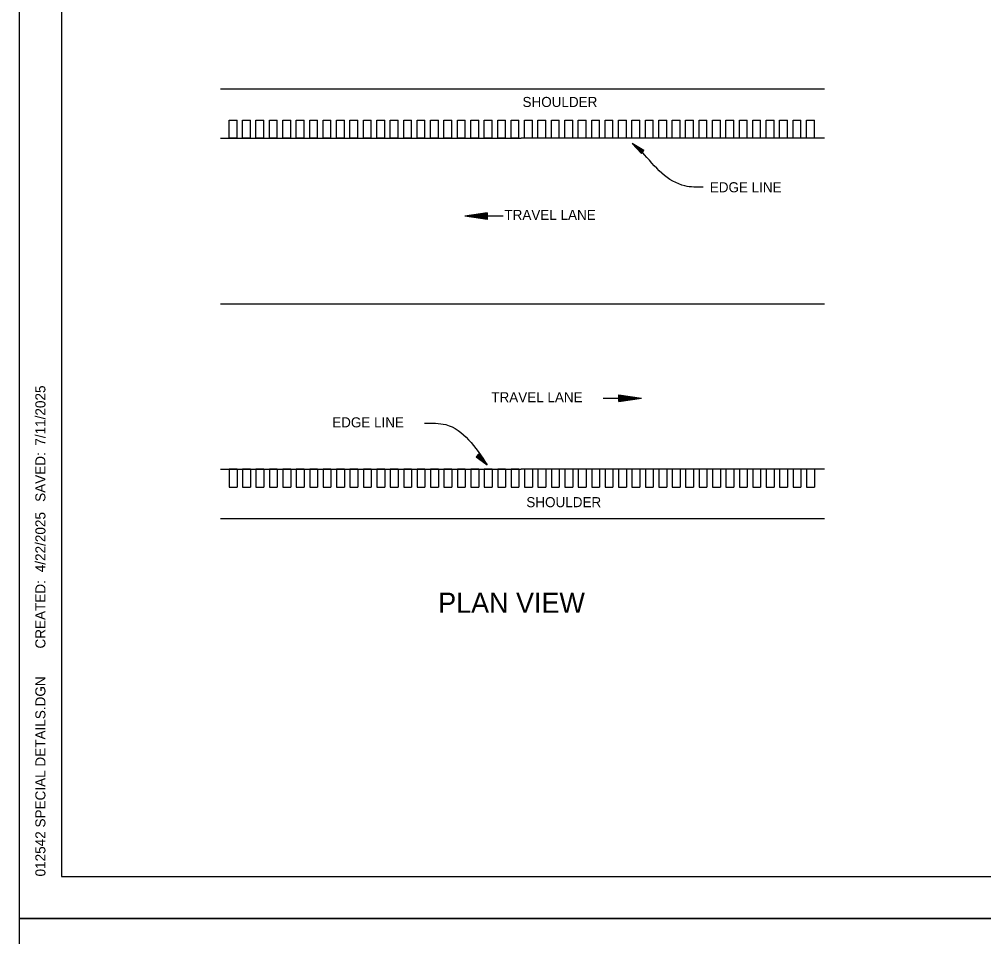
# Model space of a CAD drawing. Extents: x 1371343 to 1373043, y 378740 to 382040.
# Drawn here: x 1371343 to 1371915, y 379830 to 380374 of the extents above; entities that cross this region are included whole.
import ezdxf

# ---------------------------------------------------------------- set-up
doc = ezdxf.new("R2010")
doc.units = 0
for name, color, linetype in [('Default', 7, 'Continuous'), ('E_Existing ROW', 7, 'Continuous'), ('R_Alt Surface Annot', 7, 'Continuous')]:
    doc.layers.add(name, color=color, linetype=linetype)

msp = doc.modelspace()

# ---------------------------------------------------------------- linework, layer by layer
at = {"layer": 'Default'}
for p, q in [((1371462.15, 380332.32), (1371820.21, 380332.32)), ((1371467.32, 380303.13), (1371467.32, 380313.71)), ((1371467.32, 380313.71), (1371471.98, 380313.71)), ((1371471.98, 380303.13), (1371471.98, 380313.71)), ((1371475.28, 380303.13), (1371475.28, 380313.71)), ((1371475.28, 380313.71), (1371479.94, 380313.71)), ((1371479.94, 380303.13), (1371479.94, 380313.71)), ((1371483.24, 380303.13), (1371483.24, 380313.71)), ((1371483.24, 380313.71), (1371487.9, 380313.71)), ((1371487.9, 380303.13), (1371487.9, 380313.71)), ((1371491.2, 380303.13), (1371491.2, 380313.71)), ((1371491.2, 380313.71), (1371495.86, 380313.71)), ((1371495.86, 380303.13), (1371495.86, 380313.71)), ((1371499.16, 380303.13), (1371499.16, 380313.71)), ((1371499.16, 380313.71), (1371503.82, 380313.71)), ((1371503.82, 380303.13), (1371503.82, 380313.71)), ((1371507.12, 380303.13), (1371507.12, 380313.71)), ((1371507.12, 380313.71), (1371511.78, 380313.71)), ((1371511.78, 380303.13), (1371511.78, 380313.71)), ((1371515.08, 380303.13), (1371515.08, 380313.71)), ((1371515.08, 380313.71), (1371519.74, 380313.71)), ((1371519.74, 380303.13), (1371519.74, 380313.71)), ((1371523.04, 380303.13), (1371523.04, 380313.71)), ((1371523.04, 380313.71), (1371527.7, 380313.71)), ((1371527.7, 380303.13), (1371527.7, 380313.71)), ((1371531, 380303.13), (1371531, 380313.71)), ((1371531, 380313.71), (1371535.66, 380313.71)), ((1371535.66, 380303.13), (1371535.66, 380313.71)), ((1371538.96, 380303.13), (1371538.96, 380313.71)), ((1371538.96, 380313.71), (1371543.62, 380313.71)), ((1371543.62, 380303.13), (1371543.62, 380313.71)), ((1371546.92, 380303.13), (1371546.92, 380313.71)), ((1371546.92, 380313.71), (1371551.58, 380313.71)), ((1371551.58, 380303.13), (1371551.58, 380313.71)), ((1371554.88, 380303.13), (1371554.88, 380313.71)), ((1371554.88, 380313.71), (1371559.53, 380313.71)), ((1371559.53, 380303.13), (1371559.53, 380313.71)), ((1371562.84, 380303.13), (1371562.84, 380313.71)), ((1371562.84, 380313.71), (1371567.49, 380313.71)), ((1371567.49, 380303.13), (1371567.49, 380313.71)), ((1371570.8, 380303.13), (1371570.8, 380313.71)), ((1371570.8, 380313.71), (1371575.45, 380313.71)), ((1371575.45, 380303.13), (1371575.45, 380313.71)), ((1371578.76, 380303.13), (1371578.76, 380313.71)), ((1371578.76, 380313.71), (1371583.41, 380313.71)), ((1371583.41, 380303.13), (1371583.41, 380313.71)), ((1371586.72, 380303.13), (1371586.72, 380313.71)), ((1371586.72, 380303.13), (1371586.72, 380313.71)), ((1371586.72, 380313.71), (1371591.37, 380313.71)), ((1371591.37, 380303.13), (1371591.37, 380313.71)), ((1371594.68, 380303.13), (1371594.68, 380313.71)), ((1371594.68, 380313.71), (1371599.33, 380313.71)), ((1371599.33, 380303.13), (1371599.33, 380313.71)), ((1371602.64, 380303.13), (1371602.64, 380313.71)), ((1371602.64, 380313.71), (1371607.29, 380313.71)), ((1371607.29, 380303.13), (1371607.29, 380313.71)), ((1371610.6, 380303.13), (1371610.6, 380313.71)), ((1371610.6, 380313.71), (1371615.25, 380313.71)), ((1371615.25, 380303.13), (1371615.25, 380313.71)), ((1371618.55, 380303.13), (1371618.55, 380313.71)), ((1371618.55, 380313.71), (1371623.21, 380313.71)), ((1371623.21, 380303.13), (1371623.21, 380313.71)), ((1371626.51, 380303.13), (1371626.51, 380313.71)), ((1371626.51, 380313.71), (1371631.17, 380313.71)), ((1371631.17, 380303.13), (1371631.17, 380313.71)), ((1371634.47, 380303.13), (1371634.47, 380313.71)), ((1371634.47, 380313.71), (1371639.13, 380313.71)), ((1371639.13, 380303.13), (1371639.13, 380313.71)), ((1371642.43, 380303.13), (1371642.43, 380313.71)), ((1371642.43, 380313.71), (1371647.09, 380313.71)), ((1371647.09, 380303.13), (1371647.09, 380313.71)), ((1371650.39, 380303.13), (1371650.39, 380313.71)), ((1371650.39, 380313.71), (1371655.05, 380313.71)), ((1371655.05, 380303.13), (1371655.05, 380313.71)), ((1371658.35, 380303.13), (1371658.35, 380313.71)), ((1371658.35, 380313.71), (1371663.01, 380313.71)), ((1371663.01, 380303.13), (1371663.01, 380313.71)), ((1371666.31, 380303.13), (1371666.31, 380313.71)), ((1371666.31, 380313.71), (1371670.97, 380313.71)), ((1371670.97, 380303.13), (1371670.97, 380313.71)), ((1371674.27, 380303.13), (1371674.27, 380313.71)), ((1371674.27, 380313.71), (1371678.93, 380313.71)), ((1371678.93, 380303.13), (1371678.93, 380313.71)), ((1371682.23, 380303.13), (1371682.23, 380313.71)), ((1371682.23, 380313.71), (1371686.89, 380313.71)), ((1371686.89, 380303.13), (1371686.89, 380313.71)), ((1371690.19, 380303.13), (1371690.19, 380313.71)), ((1371690.19, 380313.71), (1371694.85, 380313.71)), ((1371694.85, 380303.13), (1371694.85, 380313.71)), ((1371698.15, 380303.13), (1371698.15, 380313.71)), ((1371698.15, 380313.71), (1371702.81, 380313.71)), ((1371702.81, 380303.13), (1371702.81, 380313.71)), ((1371706.11, 380303.13), (1371706.11, 380313.71)), ((1371706.11, 380313.71), (1371710.77, 380313.71)), ((1371710.77, 380303.13), (1371710.77, 380313.71)), ((1371714.07, 380303.13), (1371714.07, 380313.71)), ((1371714.07, 380313.71), (1371718.73, 380313.71)), ((1371718.73, 380303.13), (1371718.73, 380313.71)), ((1371722.03, 380303.13), (1371722.03, 380313.71)), ((1371722.03, 380313.71), (1371726.69, 380313.71)), ((1371726.69, 380303.13), (1371726.69, 380313.71)), ((1371729.99, 380303.13), (1371729.99, 380313.71)), ((1371729.99, 380313.71), (1371734.64, 380313.71)), ((1371734.64, 380303.13), (1371734.64, 380313.71)), ((1371737.95, 380303.13), (1371737.95, 380313.71)), ((1371737.95, 380313.71), (1371742.6, 380313.71)), ((1371742.6, 380303.13), (1371742.6, 380313.71)), ((1371745.91, 380303.13), (1371745.91, 380313.71)), ((1371745.91, 380313.71), (1371750.56, 380313.71)), ((1371750.56, 380303.13), (1371750.56, 380313.71)), ((1371753.87, 380303.13), (1371753.87, 380313.71)), ((1371753.87, 380313.71), (1371758.52, 380313.71)), ((1371758.52, 380303.13), (1371758.52, 380313.71)), ((1371761.83, 380303.13), (1371761.83, 380313.71)), ((1371761.83, 380313.71), (1371766.48, 380313.71)), ((1371766.48, 380303.13), (1371766.48, 380313.71)), ((1371769.79, 380303.13), (1371769.79, 380313.71)), ((1371769.79, 380313.71), (1371774.44, 380313.71)), ((1371774.44, 380303.13), (1371774.44, 380313.71)), ((1371777.75, 380303.13), (1371777.75, 380313.71)), ((1371777.75, 380313.71), (1371782.4, 380313.71)), ((1371782.4, 380303.13), (1371782.4, 380313.71)), ((1371785.7, 380303.13), (1371785.7, 380313.71)), ((1371785.7, 380313.71), (1371790.36, 380313.71)), ((1371790.36, 380303.13), (1371790.36, 380313.71)), ((1371793.66, 380303.13), (1371793.66, 380313.71)), ((1371793.66, 380313.71), (1371798.32, 380313.71)), ((1371798.32, 380303.13), (1371798.32, 380313.71)), ((1371801.62, 380303.13), (1371801.62, 380313.71)), ((1371801.62, 380313.71), (1371806.28, 380313.71)), ((1371806.28, 380303.13), (1371806.28, 380313.71)), ((1371809.58, 380303.13), (1371809.58, 380313.71)), ((1371809.58, 380313.71), (1371814.24, 380313.71)), ((1371814.24, 380303.13), (1371814.24, 380313.71)), ((1371462.15, 380303.13), (1371640.34, 380303.13)), ((1371471.98, 380303.13), (1371467.32, 380303.13)), ((1371479.94, 380303.13), (1371475.28, 380303.13)), ((1371487.9, 380303.13), (1371483.24, 380303.13)), ((1371495.86, 380303.13), (1371491.2, 380303.13)), ((1371503.82, 380303.13), (1371499.16, 380303.13)), ((1371511.78, 380303.13), (1371507.12, 380303.13)), ((1371519.74, 380303.13), (1371515.08, 380303.13)), ((1371527.7, 380303.13), (1371523.04, 380303.13)), ((1371535.66, 380303.13), (1371531, 380303.13)), ((1371543.62, 380303.13), (1371538.96, 380303.13)), ((1371551.58, 380303.13), (1371546.92, 380303.13)), ((1371559.53, 380303.13), (1371554.88, 380303.13)), ((1371567.49, 380303.13), (1371562.84, 380303.13)), ((1371575.45, 380303.13), (1371570.8, 380303.13)), ((1371583.41, 380303.13), (1371578.76, 380303.13)), ((1371591.37, 380303.13), (1371586.72, 380303.13)), ((1371599.33, 380303.13), (1371594.68, 380303.13)), ((1371607.29, 380303.13), (1371602.64, 380303.13)), ((1371615.25, 380303.13), (1371610.6, 380303.13)), ((1371623.21, 380303.13), (1371618.55, 380303.13)), ((1371631.17, 380303.13), (1371626.51, 380303.13)), ((1371639.13, 380303.13), (1371634.47, 380303.13)), ((1371820.21, 380303.13), (1371640.34, 380303.13)), ((1371647.09, 380303.13), (1371642.43, 380303.13)), ((1371655.05, 380303.13), (1371650.39, 380303.13)), ((1371663.01, 380303.13), (1371658.35, 380303.13)), ((1371670.97, 380303.13), (1371666.31, 380303.13)), ((1371678.93, 380303.13), (1371674.27, 380303.13)), ((1371686.89, 380303.13), (1371682.23, 380303.13)), ((1371694.85, 380303.13), (1371690.19, 380303.13)), ((1371702.81, 380303.13), (1371698.15, 380303.13)), ((1371710.77, 380303.13), (1371706.11, 380303.13)), ((1371718.73, 380303.13), (1371714.07, 380303.13)), ((1371726.69, 380303.13), (1371722.03, 380303.13)), ((1371734.64, 380303.13), (1371729.99, 380303.13)), ((1371742.6, 380303.13), (1371737.95, 380303.13)), ((1371750.56, 380303.13), (1371745.91, 380303.13)), ((1371758.52, 380303.13), (1371753.87, 380303.13)), ((1371766.48, 380303.13), (1371761.83, 380303.13)), ((1371774.44, 380303.13), (1371769.79, 380303.13)), ((1371782.4, 380303.13), (1371777.75, 380303.13)), ((1371790.36, 380303.13), (1371785.7, 380303.13)), ((1371798.32, 380303.13), (1371793.66, 380303.13)), ((1371806.28, 380303.13), (1371801.62, 380303.13)), ((1371814.24, 380303.13), (1371809.58, 380303.13)), ((1371711.7, 380293.95), (1371706.23, 380299.86)), ((1371713.19, 380295.82), (1371706.23, 380299.86)), ((1371711.82, 380294.11), (1371707.26, 380299.03)), ((1371713.07, 380295.66), (1371707.26, 380299.03)), ((1371712.93, 380295.5), (1371708.34, 380298.19)), ((1371711.96, 380294.27), (1371708.34, 380298.19)), ((1371712.08, 380294.43), (1371709.37, 380297.36)), ((1371712.82, 380295.35), (1371709.37, 380297.36)), ((1371712.68, 380295.19), (1371710.43, 380296.5)), ((1371712.2, 380294.59), (1371710.43, 380296.5)), ((1371711.7, 380293.95), (1371713.19, 380295.82)), ((1371712.56, 380295.03), (1371711.46, 380295.68)), ((1371712.32, 380294.75), (1371711.46, 380295.68)), ((1371620.37, 380258.83), (1371606.99, 380256.82)), ((1371629.76, 380256.82), (1371606.99, 380256.82)), ((1371620.37, 380254.83), (1371606.99, 380256.82)), ((1371620.37, 380258.49), (1371609.22, 380256.82)), ((1371620.37, 380255.15), (1371609.22, 380256.82)), ((1371620.37, 380258.17), (1371611.51, 380256.82)), ((1371620.37, 380255.51), (1371611.51, 380256.82)), ((1371620.37, 380257.81), (1371613.72, 380256.82)), ((1371620.37, 380255.82), (1371613.72, 380256.82)), ((1371620.37, 380257.46), (1371616.01, 380256.82)), ((1371620.37, 380256.16), (1371616.01, 380256.82)), ((1371620.37, 380257.16), (1371618.24, 380256.82)), ((1371620.37, 380256.5), (1371618.24, 380256.82)), ((1371620.37, 380258.83), (1371620.37, 380254.83)), ((1371462.15, 380204.96), (1371820.21, 380204.96)), ((1371689.04, 380149.07), (1371711.8, 380149.07)), ((1371698.43, 380151.04), (1371711.8, 380149.07)), ((1371698.43, 380147.06), (1371698.43, 380151.04)), ((1371698.43, 380150.72), (1371709.57, 380149.07)), ((1371698.43, 380150.38), (1371707.28, 380149.07)), ((1371698.43, 380150.04), (1371705.07, 380149.07)), ((1371698.43, 380149.71), (1371702.79, 380149.07)), ((1371698.43, 380149.39), (1371700.56, 380149.07)), ((1371698.43, 380147.06), (1371711.8, 380149.07)), ((1371698.43, 380148.41), (1371702.79, 380149.07)), ((1371698.43, 380147.72), (1371707.28, 380149.07)), ((1371698.43, 380147.38), (1371709.57, 380149.07)), ((1371698.43, 380148.05), (1371705.07, 380149.07)), ((1371698.43, 380148.73), (1371700.56, 380149.07)), ((1371615.37, 380115.92), (1371613.72, 380114.21)), ((1371613.72, 380114.21), (1371620.27, 380109.51)), ((1371613.86, 380114.35), (1371619.31, 380110.45)), ((1371614, 380114.49), (1371618.32, 380111.4)), ((1371614.14, 380114.62), (1371617.38, 380112.32)), ((1371614.28, 380114.76), (1371616.41, 380113.25)), ((1371614.42, 380114.92), (1371615.45, 380114.19)), ((1371614.67, 380115.18), (1371615.45, 380114.19)), ((1371614.81, 380115.32), (1371616.41, 380113.25)), ((1371614.95, 380115.48), (1371617.38, 380112.32)), ((1371615.09, 380115.62), (1371618.32, 380111.4)), ((1371615.23, 380115.76), (1371619.31, 380110.45)), ((1371615.37, 380115.92), (1371620.27, 380109.51)), ((1371462.15, 380106.8), (1371640.34, 380106.8)), ((1371471.98, 380106.8), (1371467.32, 380106.8)), ((1371467.32, 380106.8), (1371467.32, 380096.22)), ((1371471.98, 380106.8), (1371471.98, 380096.22)), ((1371479.94, 380106.8), (1371475.28, 380106.8)), ((1371475.28, 380106.8), (1371475.28, 380096.22)), ((1371479.94, 380106.8), (1371479.94, 380096.22)), ((1371487.9, 380106.8), (1371483.24, 380106.8)), ((1371483.24, 380106.8), (1371483.24, 380096.22)), ((1371487.9, 380106.8), (1371487.9, 380096.22)), ((1371495.86, 380106.8), (1371491.2, 380106.8)), ((1371491.2, 380106.8), (1371491.2, 380096.22)), ((1371495.86, 380106.8), (1371495.86, 380096.22)), ((1371503.82, 380106.8), (1371499.16, 380106.8)), ((1371499.16, 380106.8), (1371499.16, 380096.22)), ((1371503.82, 380106.8), (1371503.82, 380096.22)), ((1371511.78, 380106.8), (1371507.12, 380106.8)), ((1371507.12, 380106.8), (1371507.12, 380096.22)), ((1371511.78, 380106.8), (1371511.78, 380096.22)), ((1371519.74, 380106.8), (1371515.08, 380106.8)), ((1371515.08, 380106.8), (1371515.08, 380096.22)), ((1371519.74, 380106.8), (1371519.74, 380096.22)), ((1371527.7, 380106.8), (1371523.04, 380106.8)), ((1371523.04, 380106.8), (1371523.04, 380096.22)), ((1371527.7, 380106.8), (1371527.7, 380096.22)), ((1371535.66, 380106.8), (1371531, 380106.8)), ((1371531, 380106.8), (1371531, 380096.22)), ((1371535.66, 380106.8), (1371535.66, 380096.22)), ((1371543.62, 380106.8), (1371538.96, 380106.8)), ((1371538.96, 380106.8), (1371538.96, 380096.22)), ((1371543.62, 380106.8), (1371543.62, 380096.22)), ((1371551.58, 380106.8), (1371546.92, 380106.8)), ((1371546.92, 380106.8), (1371546.92, 380096.22)), ((1371551.58, 380106.8), (1371551.58, 380096.22)), ((1371559.53, 380106.8), (1371554.88, 380106.8)), ((1371554.88, 380106.8), (1371554.88, 380096.22)), ((1371559.53, 380106.8), (1371559.53, 380096.22)), ((1371567.49, 380106.8), (1371562.84, 380106.8)), ((1371562.84, 380106.8), (1371562.84, 380096.22)), ((1371567.49, 380106.8), (1371567.49, 380096.22)), ((1371575.45, 380106.8), (1371570.8, 380106.8)), ((1371570.8, 380106.8), (1371570.8, 380096.22)), ((1371575.45, 380106.8), (1371575.45, 380096.22)), ((1371583.41, 380106.8), (1371578.76, 380106.8)), ((1371578.76, 380106.8), (1371578.76, 380096.22)), ((1371583.41, 380106.8), (1371583.41, 380096.22)), ((1371591.37, 380106.8), (1371586.72, 380106.8)), ((1371586.72, 380106.8), (1371586.72, 380096.22)), ((1371591.37, 380106.8), (1371591.37, 380096.22)), ((1371599.33, 380106.8), (1371594.68, 380106.8)), ((1371594.68, 380106.8), (1371594.68, 380096.22)), ((1371599.33, 380106.8), (1371599.33, 380096.22)), ((1371607.29, 380106.8), (1371602.64, 380106.8)), ((1371602.64, 380106.8), (1371602.64, 380096.22)), ((1371607.29, 380106.8), (1371607.29, 380096.22)), ((1371615.25, 380106.8), (1371610.6, 380106.8)), ((1371610.6, 380106.8), (1371610.6, 380096.22)), ((1371615.25, 380106.8), (1371615.25, 380096.22)), ((1371623.21, 380106.8), (1371618.55, 380106.8)), ((1371618.55, 380106.8), (1371618.55, 380096.22)), ((1371623.21, 380106.8), (1371623.21, 380096.22)), ((1371631.17, 380106.8), (1371626.51, 380106.8)), ((1371626.51, 380106.8), (1371626.51, 380096.22)), ((1371631.17, 380106.8), (1371631.17, 380096.22)), ((1371639.13, 380106.8), (1371634.47, 380106.8)), ((1371634.47, 380106.8), (1371634.47, 380096.22)), ((1371639.13, 380106.8), (1371639.13, 380096.22)), ((1371820.21, 380106.8), (1371640.34, 380106.8)), ((1371647.09, 380106.8), (1371642.43, 380106.8)), ((1371642.43, 380106.8), (1371642.43, 380096.22)), ((1371647.09, 380106.8), (1371647.09, 380096.22)), ((1371655.05, 380106.8), (1371650.39, 380106.8)), ((1371650.39, 380106.8), (1371650.39, 380096.22)), ((1371655.05, 380106.8), (1371655.05, 380096.22)), ((1371663.01, 380106.8), (1371658.35, 380106.8)), ((1371658.35, 380106.8), (1371658.35, 380096.22)), ((1371663.01, 380106.8), (1371663.01, 380096.22)), ((1371670.97, 380106.8), (1371666.31, 380106.8)), ((1371666.31, 380106.8), (1371666.31, 380096.22)), ((1371670.97, 380106.8), (1371670.97, 380096.22)), ((1371678.93, 380106.8), (1371674.27, 380106.8)), ((1371674.27, 380106.8), (1371674.27, 380096.22)), ((1371678.93, 380106.8), (1371678.93, 380096.22)), ((1371686.89, 380106.8), (1371682.23, 380106.8)), ((1371682.23, 380106.8), (1371682.23, 380096.22)), ((1371686.89, 380106.8), (1371686.89, 380096.22)), ((1371694.85, 380106.8), (1371690.19, 380106.8)), ((1371690.19, 380106.8), (1371690.19, 380096.22)), ((1371694.85, 380106.8), (1371694.85, 380096.22)), ((1371702.81, 380106.8), (1371698.15, 380106.8)), ((1371698.15, 380106.8), (1371698.15, 380096.22)), ((1371702.81, 380106.8), (1371702.81, 380096.22)), ((1371710.77, 380106.8), (1371706.11, 380106.8)), ((1371706.11, 380106.8), (1371706.11, 380096.22)), ((1371710.77, 380106.8), (1371710.77, 380096.22)), ((1371718.73, 380106.8), (1371714.07, 380106.8)), ((1371714.07, 380106.8), (1371714.07, 380096.22)), ((1371718.73, 380106.8), (1371718.73, 380096.22)), ((1371726.69, 380106.8), (1371722.03, 380106.8)), ((1371722.03, 380106.8), (1371722.03, 380096.22)), ((1371726.69, 380106.8), (1371726.69, 380096.22)), ((1371734.64, 380106.8), (1371729.99, 380106.8)), ((1371729.99, 380106.8), (1371729.99, 380096.22)), ((1371734.64, 380106.8), (1371734.64, 380096.22)), ((1371742.6, 380106.8), (1371737.95, 380106.8)), ((1371737.95, 380106.8), (1371737.95, 380096.22)), ((1371742.6, 380106.8), (1371742.6, 380096.22)), ((1371750.56, 380106.8), (1371745.91, 380106.8)), ((1371745.91, 380106.8), (1371745.91, 380096.22)), ((1371750.56, 380106.8), (1371750.56, 380096.22)), ((1371758.52, 380106.8), (1371753.87, 380106.8)), ((1371753.87, 380106.8), (1371753.87, 380096.22)), ((1371758.52, 380106.8), (1371758.52, 380096.22)), ((1371766.48, 380106.8), (1371761.83, 380106.8)), ((1371761.83, 380106.8), (1371761.83, 380096.22)), ((1371766.48, 380106.8), (1371766.48, 380096.22)), ((1371774.44, 380106.8), (1371769.79, 380106.8)), ((1371769.79, 380106.8), (1371769.79, 380096.22)), ((1371774.44, 380106.8), (1371774.44, 380096.22)), ((1371782.4, 380106.8), (1371777.75, 380106.8)), ((1371777.75, 380106.8), (1371777.75, 380096.22)), ((1371782.4, 380106.8), (1371782.4, 380096.22)), ((1371790.36, 380106.8), (1371785.7, 380106.8)), ((1371785.7, 380106.8), (1371785.7, 380096.22)), ((1371790.36, 380106.8), (1371790.36, 380096.22)), ((1371798.32, 380106.8), (1371793.66, 380106.8)), ((1371793.66, 380106.8), (1371793.66, 380096.22)), ((1371798.32, 380106.8), (1371798.32, 380096.22)), ((1371806.28, 380106.8), (1371801.62, 380106.8)), ((1371801.62, 380106.8), (1371801.62, 380096.22)), ((1371806.28, 380106.8), (1371806.28, 380096.22)), ((1371814.24, 380106.8), (1371809.58, 380106.8)), ((1371809.58, 380106.8), (1371809.58, 380096.22)), ((1371814.24, 380106.8), (1371814.24, 380096.22)), ((1371467.32, 380096.22), (1371471.98, 380096.22)), ((1371475.28, 380096.22), (1371479.94, 380096.22)), ((1371483.24, 380096.22), (1371487.9, 380096.22)), ((1371491.2, 380096.22), (1371495.86, 380096.22)), ((1371499.16, 380096.22), (1371503.82, 380096.22)), ((1371507.12, 380096.22), (1371511.78, 380096.22)), ((1371515.08, 380096.22), (1371519.74, 380096.22)), ((1371523.04, 380096.22), (1371527.7, 380096.22)), ((1371531, 380096.22), (1371535.66, 380096.22)), ((1371538.96, 380096.22), (1371543.62, 380096.22)), ((1371546.92, 380096.22), (1371551.58, 380096.22)), ((1371554.88, 380096.22), (1371559.53, 380096.22)), ((1371562.84, 380096.22), (1371567.49, 380096.22)), ((1371570.8, 380096.22), (1371575.45, 380096.22)), ((1371578.76, 380096.22), (1371583.41, 380096.22)), ((1371586.72, 380096.22), (1371591.37, 380096.22)), ((1371594.68, 380096.22), (1371599.33, 380096.22)), ((1371602.64, 380096.22), (1371607.29, 380096.22)), ((1371610.6, 380096.22), (1371615.25, 380096.22)), ((1371618.55, 380096.22), (1371623.21, 380096.22)), ((1371626.51, 380096.22), (1371631.17, 380096.22)), ((1371634.47, 380096.22), (1371639.13, 380096.22)), ((1371642.43, 380096.22), (1371647.09, 380096.22)), ((1371650.39, 380096.22), (1371655.05, 380096.22)), ((1371658.35, 380096.22), (1371663.01, 380096.22)), ((1371666.31, 380096.22), (1371670.97, 380096.22)), ((1371674.27, 380096.22), (1371678.93, 380096.22)), ((1371682.23, 380096.22), (1371686.89, 380096.22)), ((1371690.19, 380096.22), (1371694.85, 380096.22)), ((1371698.15, 380096.22), (1371702.81, 380096.22)), ((1371706.11, 380096.22), (1371710.77, 380096.22)), ((1371714.07, 380096.22), (1371718.73, 380096.22)), ((1371722.03, 380096.22), (1371726.69, 380096.22)), ((1371729.99, 380096.22), (1371734.64, 380096.22)), ((1371737.95, 380096.22), (1371742.6, 380096.22)), ((1371745.91, 380096.22), (1371750.56, 380096.22)), ((1371753.87, 380096.22), (1371758.52, 380096.22)), ((1371761.83, 380096.22), (1371766.48, 380096.22)), ((1371769.79, 380096.22), (1371774.44, 380096.22)), ((1371777.75, 380096.22), (1371782.4, 380096.22)), ((1371785.7, 380096.22), (1371790.36, 380096.22)), ((1371793.66, 380096.22), (1371798.32, 380096.22)), ((1371801.62, 380096.22), (1371806.28, 380096.22)), ((1371809.58, 380096.22), (1371814.24, 380096.22)), ((1371462.15, 380077.61), (1371820.21, 380077.61))]:
    msp.add_line(p, q, dxfattribs=at)
for points in [[(1371748.3, 380273.99), (1371737.51, 380274.77), (1371712.16, 380294.97)], [(1371583.06, 380134.15), (1371595.73, 380133.27), (1371620.27, 380109.51)]]:
    msp.add_spline(points, degree=3, dxfattribs=at)
at = {"layer": 'E_Existing ROW'}
for points in [[(1371342.92, 379840.49), (1373042.92, 379840.49), (1373042.92, 380940.49), (1371342.92, 380940.49)], [(1371367.92, 379865.49), (1373017.92, 379865.49), (1373017.92, 380915.49), (1371367.92, 380915.49)], [(1371342.92, 378740.49), (1373042.92, 378740.49), (1373042.92, 379840.49), (1371342.92, 379840.49)]]:
    msp.add_lwpolyline(points, close=True, dxfattribs=at)

# ---------------------------------------------------------------- texts
at = {"layer": 'Default'}
for s, height, p in [('SHOULDER', 5.97, (1371641.24, 380321.55)), ('EDGE LINE', 5.97, (1371752.26, 380270.99)), ('TRAVEL LANE', 5.9696, (1371630.51, 380254.62)), ('TRAVEL LANE', 5.9696, (1371622.72, 380146.55)), ('EDGE LINE', 5.97, (1371528.39, 380131.67)), ('SHOULDER', 5.97, (1371643.51, 380084.36)), ('PLAN VIEW ', 11.939, (1371591.25, 380021.75))]:
    msp.add_text(s, height=height, dxfattribs=at).set_placement(p)
at = {"layer": 'R_Alt Surface Annot'}
for s, p in [('7/11/2025', (1371358.42, 380120.8)), ('  SAVED: ', (1371358.42, 380083.06)), ('4/22/2025', (1371358.42, 380045.79)), ('     CREATED: ', (1371358.42, 379989.43)), ('012542 SPECIAL DETAILS.DGN', (1371358.42, 379865.49))]:
    msp.add_text(s, height=6, rotation=90, dxfattribs=at).set_placement(p)

doc.saveas('drawing.dxf')
